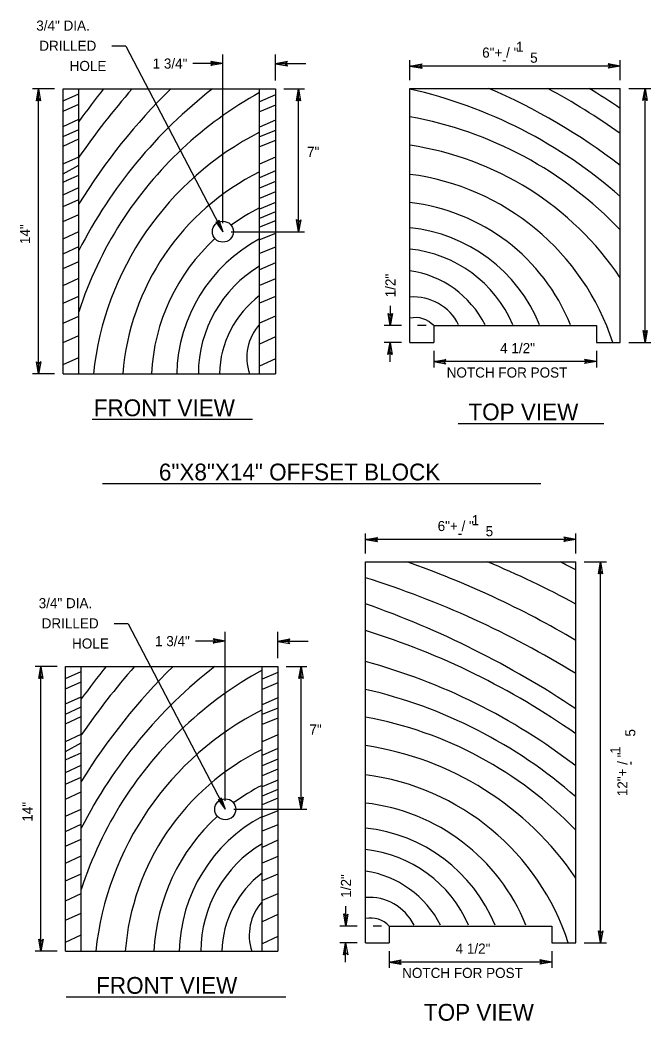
# Model space of a CAD drawing. Extents: x 12.3 to 19.6, y 6 to 16.3.
# Drawn here: x 12.39 to 16.15, y 10.15 to 16.1 of the extents above; entities that cross this region are included whole.
import ezdxf

# ---------------------------------------------------------------- set-up
doc = ezdxf.new("R2010")
doc.units = 0
for name, color, linetype in [('DETL-DIMS', 7, 'Continuous'), ('DETL-LINE', 7, 'Continuous'), ('DETL-NOTE', 7, 'Continuous'), ('DETL-PATT', 7, 'Continuous'), ('DETL-TITL', 7, 'Continuous')]:
    doc.layers.add(name, color=color, linetype=linetype)

msp = doc.modelspace()

# ---------------------------------------------------------------- linework, layer by layer
at = {"layer": 'DETL-DIMS'}
for p, q in [((13.0227, 15.9478), (12.9399, 15.9478)), ((13.0227, 15.9478), (13.6005, 14.8432)), ((13.6005, 15.8439), (13.5291, 15.8569)), ((13.5291, 15.8569), (13.5425, 15.8443)), ((13.6005, 14.8932), (13.6005, 15.8984)), ((13.9132, 15.7434), (13.9132, 15.8984)), ((13.9132, 15.8424), (13.9846, 15.8554)), ((13.9846, 15.8554), (13.9712, 15.8428)), ((14.7134, 15.7457), (14.7134, 15.864)), ((15.9641, 15.7457), (15.9641, 15.864)), ((13.6005, 15.8439), (13.4227, 15.8439)), ((13.5425, 15.8443), (13.5289, 15.8317)), ((13.6005, 15.8439), (13.5289, 15.8317)), ((13.9132, 15.8424), (13.9848, 15.8302)), ((14.0943, 15.8424), (13.9132, 15.8424)), ((13.9712, 15.8428), (13.9848, 15.8302)), ((14.7134, 15.829), (14.785, 15.8412)), ((14.7134, 15.829), (14.7848, 15.816)), ((15.9641, 15.829), (14.7134, 15.829)), ((14.7714, 15.8286), (14.785, 15.8412)), ((14.7848, 15.816), (14.7714, 15.8286)), ((15.9061, 15.8294), (15.8925, 15.8168)), ((15.9641, 15.829), (15.8925, 15.8168)), ((15.9641, 15.829), (15.8927, 15.842)), ((15.8927, 15.842), (15.9061, 15.8294)), ((12.6002, 15.6934), (12.4693, 15.6934)), ((12.5043, 15.6934), (12.4913, 15.622)), ((12.5043, 15.6934), (12.5165, 15.6218)), ((12.5043, 13.9981), (12.5043, 15.6934)), ((13.9632, 15.6934), (14.086, 15.6934)), ((14.051, 15.6934), (14.038, 15.622)), ((14.051, 15.6934), (14.0632, 15.6218)), ((14.051, 14.8432), (14.051, 15.6934)), ((16.0141, 15.6957), (16.1464, 15.6957)), ((16.1114, 15.6957), (16.0984, 15.6243)), ((16.1114, 15.6957), (16.1236, 15.6241)), ((16.1114, 14.184), (16.1114, 15.6957)), ((12.4913, 15.622), (12.5039, 15.6354)), ((12.5039, 15.6354), (12.5165, 15.6218)), ((14.038, 15.622), (14.0506, 15.6354)), ((14.0506, 15.6354), (14.0632, 15.6218)), ((16.0984, 15.6243), (16.111, 15.6377)), ((16.111, 15.6377), (16.1236, 15.6241)), ((13.5579, 14.9021), (13.6005, 14.8432)), ((13.5579, 14.9021), (13.5714, 14.899)), ((13.5765, 14.9118), (13.5714, 14.899)), ((13.5765, 14.9118), (13.6005, 14.8432)), ((14.051, 14.8432), (14.0388, 14.9148)), ((14.0514, 14.9012), (14.0388, 14.9148)), ((14.051, 14.8432), (14.064, 14.9146)), ((14.064, 14.9146), (14.0514, 14.9012)), ((13.6505, 14.8432), (14.086, 14.8432)), ((14.5964, 14.2844), (14.5972, 14.4026)), ((14.5964, 14.2844), (14.5842, 14.356)), ((14.5968, 14.3424), (14.5842, 14.356)), ((14.5964, 14.2844), (14.6094, 14.3558)), ((14.6094, 14.3558), (14.5968, 14.3424)), ((14.6634, 14.2841), (14.5605, 14.2841)), ((14.8094, 14.2841), (14.7584, 14.2841)), ((16.1114, 14.184), (16.0992, 14.2556)), ((16.1118, 14.242), (16.0992, 14.2556)), ((16.1114, 14.184), (16.1244, 14.2554)), ((16.1244, 14.2554), (16.1118, 14.242)), ((14.6634, 14.184), (14.5605, 14.184)), ((14.5955, 14.184), (14.5825, 14.1126)), ((14.5946, 14.0689), (14.5955, 14.184)), ((14.5955, 14.184), (14.6077, 14.1124)), ((16.0141, 14.184), (16.1464, 14.184)), ((14.5825, 14.1126), (14.5951, 14.126)), ((14.5951, 14.126), (14.6077, 14.1124)), ((14.8544, 14.134), (14.8544, 14.0352)), ((15.8224, 14.134), (15.8224, 14.0352)), ((12.5043, 13.9981), (12.4921, 14.0697)), ((12.5047, 14.0561), (12.4921, 14.0697)), ((12.5043, 13.9981), (12.5173, 14.0695)), ((12.5173, 14.0695), (12.5047, 14.0561)), ((14.8544, 14.0702), (14.9259, 14.0828)), ((14.8544, 14.0702), (14.9259, 14.0576)), ((15.822, 14.0702), (14.8544, 14.0702)), ((14.9124, 14.0702), (14.9259, 14.0828)), ((14.9259, 14.0576), (14.9124, 14.0702)), ((15.764, 14.0706), (15.7504, 14.058)), ((15.822, 14.0702), (15.7504, 14.058)), ((15.822, 14.0702), (15.7506, 14.0832)), ((15.7506, 14.0832), (15.764, 14.0706)), ((12.6002, 13.9981), (12.4693, 13.9981)), ((14.4487, 12.9283), (14.4487, 13.0466)), ((15.6994, 12.9283), (15.6994, 13.0466)), ((14.4487, 13.0116), (14.5203, 13.0238)), ((14.4487, 13.0116), (14.5201, 12.9986)), ((15.6994, 13.0116), (14.4487, 13.0116)), ((14.5067, 13.0112), (14.5203, 13.0238)), ((14.5201, 12.9986), (14.5067, 13.0112)), ((15.6414, 13.012), (15.6278, 12.9994)), ((15.6994, 13.0116), (15.6278, 12.9994)), ((15.6994, 13.0116), (15.628, 13.0246)), ((15.628, 13.0246), (15.6414, 13.012)), ((15.7494, 12.8783), (15.8817, 12.8783)), ((15.8467, 12.8783), (15.8337, 12.8069)), ((15.8467, 12.8783), (15.8589, 12.8067)), ((15.8467, 10.6108), (15.8467, 12.8783)), ((15.8337, 12.8069), (15.8463, 12.8203)), ((15.8463, 12.8203), (15.8589, 12.8067)), ((13.037, 12.5105), (12.9542, 12.5105)), ((13.037, 12.5105), (13.6148, 11.4058)), ((13.6148, 11.4558), (13.6148, 12.4611)), ((13.9275, 12.306), (13.9275, 12.4611)), ((13.6148, 12.4066), (13.437, 12.4066)), ((13.5568, 12.407), (13.5432, 12.3944)), ((13.6148, 12.4066), (13.5432, 12.3944)), ((13.6148, 12.4066), (13.5434, 12.4196)), ((13.5434, 12.4196), (13.5568, 12.407)), ((13.9275, 12.4051), (13.9989, 12.4181)), ((13.9275, 12.4051), (13.9991, 12.3929)), ((14.1086, 12.4051), (13.9275, 12.4051)), ((13.9989, 12.4181), (13.9855, 12.4055)), ((13.9855, 12.4055), (13.9991, 12.3929)), ((12.6145, 12.256), (12.4836, 12.256)), ((12.5186, 12.256), (12.5056, 12.1846)), ((12.5186, 12.256), (12.5308, 12.1844)), ((12.5186, 10.5607), (12.5186, 12.256)), ((13.9775, 12.256), (14.1003, 12.256)), ((14.0653, 12.256), (14.0523, 12.1846)), ((14.0653, 12.256), (14.0775, 12.1844)), ((14.0653, 11.4058), (14.0653, 12.256)), ((12.5056, 12.1846), (12.5182, 12.198)), ((12.5182, 12.198), (12.5308, 12.1844)), ((14.0523, 12.1846), (14.0649, 12.198)), ((14.0649, 12.198), (14.0775, 12.1844)), ((13.5722, 11.4647), (13.6148, 11.4058)), ((13.5722, 11.4647), (13.5857, 11.4616)), ((13.5908, 11.4745), (13.5857, 11.4616)), ((13.5908, 11.4745), (13.6148, 11.4058)), ((14.0653, 11.4058), (14.0531, 11.4774)), ((14.0657, 11.4638), (14.0531, 11.4774)), ((14.0653, 11.4058), (14.0783, 11.4772)), ((14.0783, 11.4772), (14.0657, 11.4638)), ((13.6648, 11.4058), (14.1003, 11.4058)), ((14.3317, 10.7112), (14.3195, 10.7828)), ((14.3321, 10.7692), (14.3195, 10.7828)), ((14.3317, 10.7112), (14.3325, 10.8294)), ((14.3317, 10.7112), (14.3447, 10.7826)), ((14.3447, 10.7826), (14.3321, 10.7692)), ((14.3987, 10.7109), (14.2958, 10.7109)), ((14.5447, 10.7109), (14.4937, 10.7109)), ((15.8467, 10.6108), (15.8345, 10.6824)), ((15.8471, 10.6688), (15.8345, 10.6824)), ((15.8467, 10.6108), (15.8597, 10.6822)), ((15.8597, 10.6822), (15.8471, 10.6688)), ((12.5186, 10.5607), (12.5064, 10.6323)), ((12.519, 10.6187), (12.5064, 10.6323)), ((12.5186, 10.5607), (12.5316, 10.6321)), ((12.5316, 10.6321), (12.519, 10.6187)), ((14.3987, 10.6108), (14.2958, 10.6108)), ((14.3308, 10.6108), (14.3178, 10.5394)), ((14.3299, 10.4957), (14.3308, 10.6108)), ((14.3308, 10.6108), (14.343, 10.5392)), ((15.7494, 10.6108), (15.8817, 10.6108)), ((12.6145, 10.5607), (12.4836, 10.5607)), ((14.3178, 10.5394), (14.3304, 10.5528)), ((14.3304, 10.5528), (14.343, 10.5392)), ((14.5897, 10.5608), (14.5897, 10.462)), ((15.5577, 10.5608), (15.5577, 10.462)), ((14.5897, 10.497), (14.6612, 10.5096)), ((14.5897, 10.497), (14.6612, 10.4844)), ((15.5573, 10.497), (14.5897, 10.497)), ((14.6477, 10.497), (14.6612, 10.5096)), ((14.6612, 10.4844), (14.6477, 10.497)), ((15.4993, 10.4974), (15.4857, 10.4848)), ((15.5573, 10.497), (15.4857, 10.4848)), ((15.5573, 10.497), (15.4859, 10.51)), ((15.4859, 10.51), (15.4993, 10.4974))]:
    msp.add_line(p, q, dxfattribs=at)
for points in [[(13.5291, 15.8569), (13.6005, 15.8439), (13.5289, 15.8317), (13.5425, 15.8443)], [(13.9846, 15.8554), (13.9132, 15.8424), (13.9848, 15.8302), (13.9712, 15.8428)], [(14.7848, 15.816), (14.7134, 15.829), (14.785, 15.8412), (14.7714, 15.8286)], [(15.8927, 15.842), (15.9641, 15.829), (15.8925, 15.8168), (15.9061, 15.8294)], [(12.4913, 15.622), (12.5043, 15.6934), (12.5165, 15.6218), (12.5039, 15.6354)], [(14.038, 15.622), (14.051, 15.6934), (14.0632, 15.6218), (14.0506, 15.6354)], [(16.0984, 15.6243), (16.1114, 15.6957), (16.1236, 15.6241), (16.111, 15.6377)], [(14.064, 14.9146), (14.051, 14.8432), (14.0388, 14.9148), (14.0514, 14.9012)], [(14.6094, 14.3558), (14.5964, 14.2844), (14.5842, 14.356), (14.5968, 14.3424)], [(16.1244, 14.2554), (16.1114, 14.184), (16.0992, 14.2556), (16.1118, 14.242)], [(14.5825, 14.1126), (14.5955, 14.184), (14.6077, 14.1124), (14.5951, 14.126)], [(12.5173, 14.0695), (12.5043, 13.9981), (12.4921, 14.0697), (12.5047, 14.0561)], [(14.9259, 14.0576), (14.8544, 14.0702), (14.9259, 14.0828), (14.9124, 14.0702)], [(15.7506, 14.0832), (15.822, 14.0702), (15.7504, 14.058), (15.764, 14.0706)], [(14.5201, 12.9986), (14.4487, 13.0116), (14.5203, 13.0238), (14.5067, 13.0112)], [(15.628, 13.0246), (15.6994, 13.0116), (15.6278, 12.9994), (15.6414, 13.012)], [(15.8337, 12.8069), (15.8467, 12.8783), (15.8589, 12.8067), (15.8463, 12.8203)], [(13.5434, 12.4196), (13.6148, 12.4066), (13.5432, 12.3944), (13.5568, 12.407)], [(13.9989, 12.4181), (13.9275, 12.4051), (13.9991, 12.3929), (13.9855, 12.4055)], [(12.5056, 12.1846), (12.5186, 12.256), (12.5308, 12.1844), (12.5182, 12.198)], [(14.0523, 12.1846), (14.0653, 12.256), (14.0775, 12.1844), (14.0649, 12.198)], [(14.0783, 11.4772), (14.0653, 11.4058), (14.0531, 11.4774), (14.0657, 11.4638)], [(14.3447, 10.7826), (14.3317, 10.7112), (14.3195, 10.7828), (14.3321, 10.7692)], [(15.8597, 10.6822), (15.8467, 10.6108), (15.8345, 10.6824), (15.8471, 10.6688)], [(12.5316, 10.6321), (12.5186, 10.5607), (12.5064, 10.6323), (12.519, 10.6187)], [(14.3178, 10.5394), (14.3308, 10.6108), (14.343, 10.5392), (14.3304, 10.5528)], [(14.6612, 10.4844), (14.5897, 10.497), (14.6612, 10.5096), (14.6477, 10.497)], [(15.4859, 10.51), (15.5573, 10.497), (15.4857, 10.4848), (15.4993, 10.4974)]]:
    msp.add_lwpolyline(points, close=True, dxfattribs=at)
at = {"layer": 'DETL-LINE'}
for p, q in [((12.6502, 13.9981), (12.6502, 15.6934)), ((12.6502, 15.6934), (13.9132, 15.6934)), ((12.7443, 14), (12.7443, 15.6934)), ((13.8191, 14.0001), (13.8191, 15.6934)), ((13.9132, 15.6934), (13.9132, 13.9981)), ((14.7134, 14.184), (14.7134, 15.6957)), ((14.7134, 15.6957), (15.9641, 15.6957)), ((15.9641, 14.184), (15.9641, 15.6957)), ((14.8544, 14.2841), (15.8224, 14.2841)), ((14.8544, 14.2841), (14.8544, 14.184)), ((15.8224, 14.2841), (15.8224, 14.184)), ((14.7134, 14.184), (14.8544, 14.184)), ((15.8224, 14.184), (15.9641, 14.184)), ((12.6502, 13.9981), (13.9132, 13.9981)), ((14.4487, 10.6108), (14.4487, 12.8783)), ((14.4487, 12.8783), (15.6994, 12.8783)), ((15.6994, 10.6108), (15.6994, 12.8783)), ((12.6645, 10.5607), (12.6645, 12.256)), ((12.6645, 12.256), (13.9275, 12.256)), ((12.7586, 10.5626), (12.7586, 12.256)), ((13.8334, 10.5627), (13.8334, 12.256)), ((13.9275, 12.256), (13.9275, 10.5607)), ((14.5897, 10.7109), (15.5577, 10.7109)), ((14.5897, 10.7109), (14.5897, 10.6108)), ((15.5577, 10.7109), (15.5577, 10.6108)), ((14.4487, 10.6108), (14.5897, 10.6108)), ((15.5577, 10.6108), (15.6994, 10.6108)), ((12.6645, 10.5607), (13.9275, 10.5607))]:
    msp.add_line(p, q, dxfattribs=at)
for centre in [(13.6005, 14.8432), (13.6148, 11.4058)]:
    msp.add_circle(centre, 0.0625, dxfattribs=at)
at = {"layer": 'DETL-PATT'}
for p, q in [((12.6502, 15.6217), (12.7443, 15.6641)), ((13.9132, 15.6582), (13.8191, 15.617)), ((12.6502, 15.5603), (12.7443, 15.6024)), ((13.9132, 15.5952), (13.8191, 15.5559)), ((12.6502, 15.47), (12.7443, 15.5127)), ((13.9132, 15.5068), (13.8191, 15.4655)), ((12.6502, 15.4099), (12.7443, 15.452)), ((13.9132, 15.4452), (13.8191, 15.4071)), ((12.6502, 15.3523), (12.7443, 15.3951)), ((13.9132, 15.3859), (13.8191, 15.3476)), ((12.6502, 15.2474), (12.7443, 15.2896)), ((13.9132, 15.2858), (13.8191, 15.245)), ((12.6502, 15.1881), (12.7443, 15.2388)), ((13.9132, 15.2051), (13.8191, 15.1631)), ((12.6502, 15.1374), (12.7022, 15.161)), ((12.6716, 15.1471), (12.7443, 15.1799)), ((13.9132, 15.1425), (13.8191, 15.1024)), ((12.6502, 15.0628), (12.7443, 15.1054)), ((13.9132, 15.0813), (13.8191, 15.0414)), ((12.6502, 14.9928), (12.7443, 15.0352)), ((13.9132, 15.0163), (13.8191, 14.9769)), ((13.9132, 14.9615), (13.8191, 14.9223)), ((12.6502, 14.9037), (12.7443, 14.9462)), ((13.9132, 14.9086), (13.8191, 14.8693)), ((12.6502, 14.8017), (12.7443, 14.8442)), ((13.9132, 14.8331), (13.8191, 14.7954)), ((12.6502, 14.712), (12.7443, 14.7541)), ((13.9132, 14.7517), (13.8191, 14.7136)), ((12.6502, 14.6238), (12.7443, 14.6662)), ((13.9132, 14.6587), (13.8191, 14.6164)), ((12.6502, 14.5231), (12.7443, 14.5657)), ((13.9132, 14.5632), (13.8191, 14.5225)), ((12.6502, 14.4178), (12.7443, 14.4599)), ((13.9132, 14.4581), (13.8191, 14.4172)), ((12.6502, 14.2992), (12.7443, 14.3414)), ((13.9132, 14.3401), (13.8191, 14.2996)), ((12.6502, 14.183), (12.7443, 14.225)), ((13.9132, 14.2177), (13.8191, 14.1732)), ((12.6502, 14.0533), (12.7443, 14.0953)), ((13.9132, 14.0862), (13.8191, 14.0433)), ((12.6645, 12.1843), (12.7586, 12.2267)), ((13.9275, 12.2208), (13.8334, 12.1796)), ((12.6645, 12.1229), (12.7586, 12.165)), ((13.9275, 12.1578), (13.8334, 12.1185)), ((12.6645, 12.0326), (12.7586, 12.0753)), ((13.9275, 12.0694), (13.8334, 12.0281)), ((12.6645, 11.9725), (12.7586, 12.0146)), ((13.9275, 12.0078), (13.8334, 11.9697)), ((12.6645, 11.9149), (12.7586, 11.9577)), ((13.9275, 11.9485), (13.8334, 11.9102)), ((12.6645, 11.81), (12.7586, 11.8522)), ((12.6645, 11.7507), (12.7586, 11.8014)), ((13.9275, 11.8484), (13.8334, 11.8076)), ((12.6859, 11.7097), (12.7586, 11.7425)), ((13.9275, 11.7677), (13.8334, 11.7257)), ((12.6645, 11.7), (12.7165, 11.7236)), ((13.9275, 11.7051), (13.8334, 11.665)), ((12.6645, 11.6254), (12.7586, 11.668)), ((13.9275, 11.6439), (13.8334, 11.604)), ((12.6645, 11.5554), (12.7586, 11.5978)), ((13.9275, 11.5789), (13.8334, 11.5395)), ((12.6645, 11.4663), (12.7586, 11.5088)), ((13.9275, 11.5241), (13.8334, 11.4849)), ((13.9275, 11.4712), (13.8334, 11.4319)), ((12.6645, 11.3643), (12.7586, 11.4068)), ((13.9275, 11.3957), (13.8334, 11.358)), ((12.6645, 11.2746), (12.7586, 11.3167)), ((13.9275, 11.3143), (13.8334, 11.2762)), ((12.6645, 11.1864), (12.7586, 11.2288)), ((13.9275, 11.2213), (13.8334, 11.179)), ((12.6645, 11.0857), (12.7586, 11.1283)), ((13.9275, 11.1258), (13.8334, 11.0851)), ((12.6645, 10.9804), (12.7586, 11.0225)), ((13.9275, 11.0207), (13.8334, 10.9798)), ((12.6645, 10.8618), (12.7586, 10.904)), ((13.9275, 10.9027), (13.8334, 10.8622)), ((12.6645, 10.7456), (12.7586, 10.7876)), ((13.9275, 10.7803), (13.8334, 10.7358)), ((12.6645, 10.6159), (12.7586, 10.6579)), ((13.9275, 10.6488), (13.8334, 10.6059))]:
    msp.add_line(p, q, dxfattribs=at)
for centre, radius, start, end in [((15.2945, 13.4341), 2.861, 127.84619, 153.04419), ((15.7917, 13.1367), 3.5763, 134.36598, 148.44215), ((16.426, 12.7502), 4.4703, 138.8248, 145.4431), ((17.2672, 12.218), 5.5879, 141.54206, 144.03771), ((14.9235, 13.6661), 2.2888, 118.84814, 147.45682), ((14.0757, 12.9033), 2.861, 48.69667, 77.12093), ((13.7783, 12.4061), 3.5763, 52.32399, 66.90243), ((13.3918, 11.7719), 4.4703, 54.87166, 61.37142), ((12.8596, 10.9306), 5.5879, 56.24953, 58.51186), ((14.3077, 13.2743), 2.2888, 43.64042, 79.79061), ((14.6514, 13.8039), 1.8311, 117.03521, 173.91371), ((14.4455, 13.5464), 1.8311, 33.96674, 81.58668), ((14.4662, 13.8846), 1.4648, 116.21519, 175.55933), ((14.5262, 13.7316), 1.4648, 17.98894, 82.65836), ((14.5803, 13.8518), 1.1719, 21.94316, 83.47891), ((14.3461, 13.9387), 1.1719, 116.71978, 126.44263), ((14.9235, 13.6661), 2.2888, 147.45682, 162.19019), ((14.6164, 13.9345), 0.9375, 22.25978, 84.0605), ((14.3461, 13.9387), 1.1719, 132.55436, 177.09842), ((14.2633, 13.9748), 0.9375, 118.27686, 178.57934), ((14.6367, 13.9932), 0.75, 23.28884, 84.13269), ((14.2047, 13.9952), 0.75, 120.93224, 179.77838), ((14.6248, 14.0178), 0.6, 26.94704, 81.51069), ((14.18, 13.9833), 0.6, 126.97657, 178.58587), ((14.7346, 14.1548), 0.3, 26.7223, 94.06425), ((14.7445, 14.182), 0.15, 42.90712, 101.97833), ((14.043, 14.0931), 0.3, 138.27176, 198.46754), ((12.8522, 7.603), 5.5879, 59.36733, 70.74334), ((13.0333, 7.7166), 5.5879, 61.50277, 67.47683), ((13.1348, 7.8664), 5.5879, 62.67977, 63.75505), ((12.7725, 7.4532), 5.5879, 58.41283, 72.54398), ((12.5949, 7.3574), 5.5879, 56.24953, 70.62464), ((13.1271, 8.1986), 4.4703, 54.87166, 72.8045), ((13.5136, 8.8329), 3.5763, 52.32399, 74.84242), ((15.3088, 9.9968), 2.861, 127.84619, 153.04419), ((15.806, 9.6994), 3.5763, 134.36598, 148.44215), ((16.4403, 9.3129), 4.4703, 138.8248, 145.4431), ((17.2815, 8.7807), 5.5879, 141.54206, 144.03771), ((14.9378, 10.2288), 2.2888, 118.84814, 147.45682), ((13.811, 9.3301), 2.861, 48.69667, 77.12093), ((14.6657, 10.3666), 1.8311, 117.03521, 173.91371), ((14.043, 9.7011), 2.2888, 43.64042, 79.79061), ((14.4805, 10.4473), 1.4648, 116.21519, 175.55933), ((14.1808, 9.9732), 1.8311, 33.96674, 81.58668), ((14.2615, 10.1584), 1.4648, 17.98894, 82.65836), ((14.3604, 10.5014), 1.1719, 116.71978, 126.44263), ((14.9378, 10.2288), 2.2888, 147.45682, 162.19019), ((14.3156, 10.2786), 1.1719, 21.94316, 83.47891), ((14.3604, 10.5014), 1.1719, 132.55436, 177.09842), ((14.2776, 10.5375), 0.9375, 118.27686, 178.57934), ((14.3517, 10.3613), 0.9375, 22.25978, 84.0605), ((14.219, 10.5578), 0.75, 120.93224, 179.77838), ((14.3721, 10.4199), 0.75, 23.28884, 84.13269), ((14.1943, 10.5459), 0.6, 126.97657, 178.58587), ((14.3602, 10.4446), 0.6, 26.94704, 81.51069), ((14.0573, 10.6557), 0.3, 138.27176, 198.46754), ((14.47, 10.5816), 0.3, 26.7223, 94.06425), ((14.4799, 10.6088), 0.15, 42.90712, 101.97833)]:
    msp.add_arc(centre, radius, start, end, dxfattribs=at)
at = {"layer": 'DETL-TITL'}
for p, q in [((12.8225, 13.7267), (13.7759, 13.7267)), ((14.9994, 13.7022), (15.8669, 13.7022)), ((12.8852, 13.3445), (15.4907, 13.3445)), ((12.6688, 10.2893), (13.9749, 10.2893))]:
    msp.add_line(p, q, dxfattribs=at)

# ---------------------------------------------------------------- texts
at = {"layer": 'DETL-NOTE'}
for s, p in [('3/4" DIA.', (12.4909, 16.0397)), ('DRILLED', (12.5089, 15.9197)), ('1', (15.3444, 15.9137)), ('6"+ / "', (15.1425, 15.879)), ('5', (15.4279, 15.8486)), ('HOLE', (12.6895, 15.7997)), ('1 3/4" ', (13.1828, 15.8139)), ('-', (15.2618, 15.8368)), ('7" ', (14.101, 15.2883)), ('4 1/2"', (15.2495, 14.1201)), ('NOTCH FOR POST', (14.9315, 13.9752)), ('6"+ / "', (14.8778, 13.0616)), ('1', (15.0797, 13.0963)), ('-', (14.9971, 13.0194)), ('5', (15.1632, 13.0312)), ('3/4" DIA.', (12.5052, 12.6024)), ('DRILLED', (12.5232, 12.4824)), ('HOLE', (12.7038, 12.3624)), ('1 3/4" ', (13.1971, 12.3766)), ('7" ', (14.1153, 11.8509)), ('4 1/2"', (14.9848, 10.5469)), ('NOTCH FOR POST', (14.6668, 10.402))]:
    msp.add_text(s, height=0.06, dxfattribs=at).set_placement(p)
for s, p in [('14"', (12.4543, 14.7694)), ('1/2"', (14.6272, 14.4526)), ('5', (16.0536, 11.8385)), ('1', (15.9647, 11.7362)), ('12"+ / "', (16.0067, 11.4838)), ('-', (16.0506, 11.667)), ('14"', (12.4686, 11.332)), ('1/2"', (14.3625, 10.8794))]:
    msp.add_text(s, height=0.06, rotation=90, dxfattribs=at).set_placement(p)
at = {"layer": 'DETL-TITL'}
for s, p in [('FRONT VIEW', (12.8327, 13.7452)), ('TOP VIEW', (15.0608, 13.7207)), ('6"X8"X14" OFFSET BLOCK', (13.2202, 13.363)), ('FRONT VIEW', (12.847, 10.3078)), ('TOP VIEW', (14.7962, 10.1474))]:
    msp.add_text(s, height=0.1, dxfattribs=at).set_placement(p)

doc.saveas('drawing.dxf')
